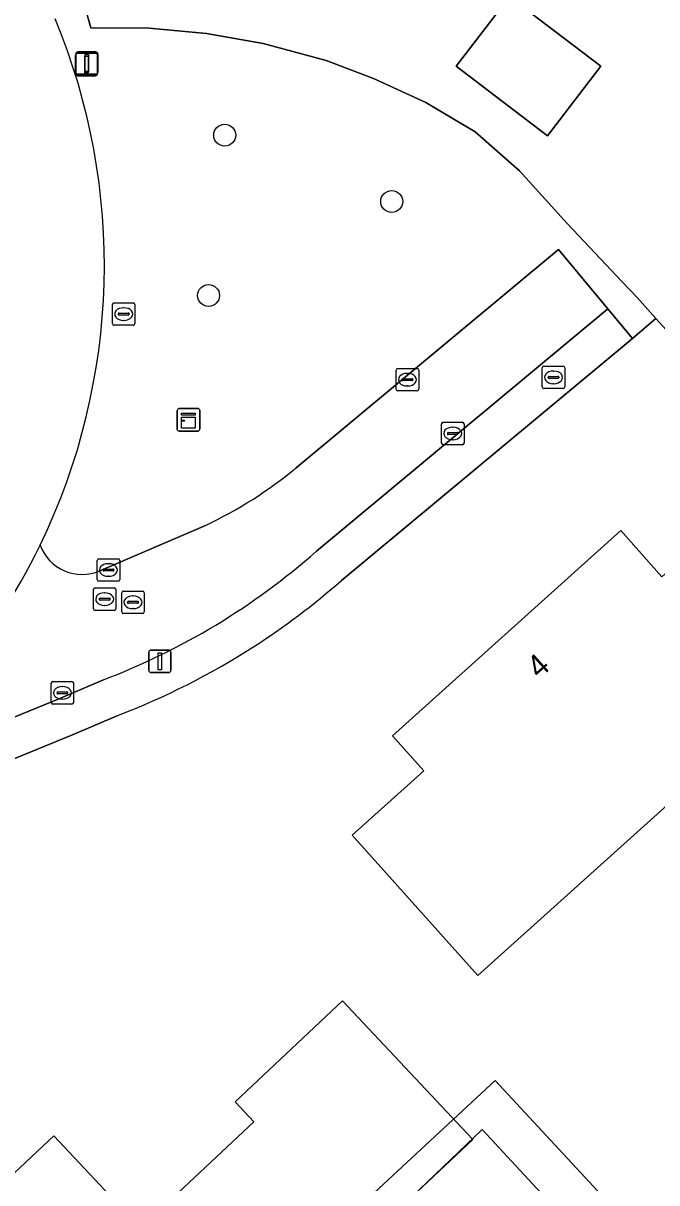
# Model space of a CAD drawing. Extents: x 163266 to 164362, y 381528 to 382286.
# Drawn here: x 163853.6 to 163881.8, y 381685.3 to 381736.9 of the extents above; entities that cross this region are included whole.
import ezdxf

# ---------------------------------------------------------------- set-up
doc = ezdxf.new("R2010")
doc.units = 0
for name, color, linetype in [('IMGEO_Boom', 7, 'Continuous'), ('IMGEO_Brandkraan', 7, 'Continuous'), ('IMGEO_Erf', 7, 'Continuous'), ('IMGEO_Groenvoorziening', 7, 'Continuous'), ('IMGEO_Hek', 7, 'Continuous'), ('IMGEO_Kast', 7, 'Continuous'), ('IMGEO_Kolk', 7, 'Continuous'), ('IMGEO_Lichtmast', 7, 'Continuous'), ('IMGEO_Pand', 7, 'Continuous'), ('IMGEO_Pand_nummerreeks', 7, 'Continuous'), ('IMGEO_Pand_vergunning_verleend', 7, 'Continuous'), ('IMGEO_Rijbaan_lokaal_gesloten', 7, 'Continuous'), ('IMGEO_Rijbaan_lokaal_open', 7, 'Continuous'), ('IMGEO_Rioolput', 7, 'Continuous'), ('IMGEO_Voetpad_open', 7, 'Continuous')]:
    doc.layers.add(name, color=color, linetype=linetype)

msp = doc.modelspace()

# ---------------------------------------------------------------- linework, layer by layer
at = {"layer": 'IMGEO_Boom'}
for centre in [(163862.574, 381731.873), (163870.006, 381728.922), (163861.854, 381724.742)]:
    msp.add_circle(centre, 0.489, dxfattribs=at)
at = {"layer": 'IMGEO_Brandkraan'}
for p, q in [((163857.578, 381723.488), (163857.578, 381724.34)), ((163857.653, 381724.414), (163858.505, 381724.414)), ((163858.066, 381724.194), (163858.091, 381724.194)), ((163858.579, 381724.34), (163858.579, 381723.488)), ((163857.837, 381723.908), (163857.837, 381723.92)), ((163858.275, 381723.871), (163857.877, 381723.871)), ((163857.88, 381723.957), (163858.278, 381723.957)), ((163858.321, 381723.92), (163858.321, 381723.908)), ((163858.505, 381723.414), (163857.653, 381723.414)), ((163858.089, 381723.634), (163858.064, 381723.634)), ((163876.705, 381720.671), (163876.705, 381721.523)), ((163876.78, 381721.597), (163877.632, 381721.597)), ((163876.964, 381721.091), (163876.964, 381721.103)), ((163877.007, 381721.14), (163877.405, 381721.14)), ((163877.193, 381721.377), (163877.218, 381721.377)), ((163877.448, 381721.103), (163877.448, 381721.091)), ((163877.706, 381721.523), (163877.706, 381720.671)), ((163877.632, 381720.597), (163876.78, 381720.597)), ((163877.402, 381721.054), (163877.004, 381721.054)), ((163877.216, 381720.817), (163877.191, 381720.817))]:
    msp.add_line(p, q, dxfattribs=at)
for points in [[(163857.578, 381723.488), (163857.578, 381724.34)], [(163857.653, 381724.414), (163858.505, 381724.414)], [(163858.579, 381724.34), (163858.579, 381723.488)], [(163858.505, 381723.414), (163857.653, 381723.414)], [(163876.705, 381720.671), (163876.705, 381721.523)], [(163876.78, 381721.597), (163877.632, 381721.597)], [(163877.706, 381721.523), (163877.706, 381720.671)], [(163877.632, 381720.597), (163876.78, 381720.597)]]:
    msp.add_lwpolyline(points, dxfattribs=at)
for centre, radius, start, end in [((163857.655, 381724.338), 0.0765, 91.552, 178.448), ((163857.655, 381724.338), 0.0765, 91.552, 178.448), ((163858.503, 381724.338), 0.0765, 1.552, 88.448), ((163858.503, 381724.338), 0.0765, 1.552, 88.448), ((163857.877, 381723.917), 0.0403, 85.8775, 175.7526), ((163857.874, 381723.907), 0.0366, 178.938, 274.7102), ((163858.278, 381723.914), 0.043, 264.8664, 352.4533), ((163858.282, 381723.919), 0.0386, 1.7309, 96.639), ((163857.655, 381723.49), 0.0765, 181.552, 268.448), ((163857.655, 381723.49), 0.0765, 181.552, 268.448), ((163858.503, 381723.49), 0.0765, 271.552, 358.448), ((163858.503, 381723.49), 0.0765, 271.552, 358.448), ((163876.782, 381721.521), 0.0765, 91.552, 178.448), ((163876.782, 381721.521), 0.0765, 91.552, 178.448), ((163877.004, 381721.1), 0.0403, 85.8775, 175.7526), ((163877.001, 381721.09), 0.0366, 178.938, 274.7102), ((163877.405, 381721.097), 0.043, 264.8664, 352.4533), ((163877.409, 381721.102), 0.0386, 1.7309, 96.639), ((163877.63, 381721.521), 0.0765, 1.552, 88.448), ((163877.63, 381721.521), 0.0765, 1.552, 88.448), ((163876.782, 381720.673), 0.0765, 181.552, 268.448), ((163876.782, 381720.673), 0.0765, 181.552, 268.448), ((163877.63, 381720.673), 0.0765, 271.552, 358.448), ((163877.63, 381720.673), 0.0765, 271.552, 358.448)]:
    msp.add_arc(centre, radius, start, end, dxfattribs=at)
for centre, major_axis, ratio, start_param, end_param in [((163858.065, 381723.914), (-0.387, 0.002), 0.722429, 4.712389, 7.853982), ((163858.09, 381723.914), (-0.39, 0.002), 0.717154, 1.570796, 4.712389), ((163877.192, 381721.097), (-0.387, 0.002), 0.722429, 4.712389, 7.853982), ((163877.217, 381721.097), (-0.39, 0.002), 0.717154, 1.570796, 4.712389)]:
    msp.add_ellipse(centre, major_axis=major_axis, ratio=ratio, start_param=start_param, end_param=end_param, dxfattribs=at)
at = {"layer": 'IMGEO_Erf'}
for points in [[(163850.883, 381757.141), (163856.616, 381736.644), (163859.21, 381736.627), (163861.761, 381736.402), (163864.289, 381735.951), (163867.084, 381735.196), (163869.192, 381734.396), (163871.524, 381733.322), (163873.711, 381732.021), (163875.685, 381730.29), (163877.82, 381727.931), (163880.26, 381725.345), (163880.92, 381724.646), (163881.763, 381723.722), (163902.744, 381700.712)], [(163813.536, 381684.558), (163844.648, 381661.7), (163845.156, 381661.33), (163866.027, 381679.982), (163874.024, 381687.636), (163880.414, 381680.758), (163881.837, 381682.029), (163902.744, 381700.712), (163881.763, 381723.722)], [(163881.763, 381723.722), (163880.716, 381722.833), (163867.763, 381712.065)], [(163857.819, 381706.063), (163855.804, 381705.198), (163814.888, 381688.458)], [(163880.414, 381680.758), (163874.024, 381687.636), (163866.027, 381679.982)]]:
    msp.add_lwpolyline(points, dxfattribs=at)
for points in [[(163876.932, 381731.837), (163872.867, 381734.948), (163875.238, 381738.047), (163879.303, 381734.936)], [(163880.198, 381714.282), (163882.017, 381712.229), (163886.456, 381716.202), (163895.326, 381706.295), (163894.818, 381705.864), (163894.515, 381706.203), (163894.839, 381706.494), (163892.959, 381708.595), (163890.6, 381706.433), (163890.157, 381706.93), (163888.281, 381705.256), (163888.721, 381704.764), (163888.381, 381704.461), (163886.839, 381706.189), (163873.843, 381694.498), (163868.244, 381700.731), (163871.439, 381703.601), (163870.041, 381705.157)]]:
    msp.add_lwpolyline(points, close=True, dxfattribs=at)
for centre, radius, start, end in [((163846.239, 381736.522), 32.58, 302.6721, 311.3512), ((163846.046, 381736.837), 32.949, 290.9359, 302.6588)]:
    msp.add_arc(centre, radius, start, end, dxfattribs=at)
at = {"layer": 'IMGEO_Groenvoorziening'}
for points in [[(163873.711, 381732.021), (163871.524, 381733.322), (163869.192, 381734.396), (163867.084, 381735.196), (163864.289, 381735.951), (163861.761, 381736.402), (163859.21, 381736.627), (163856.616, 381736.644), (163850.883, 381757.141), (163850.503, 381759.694), (163850.811, 381762.261), (163851.842, 381764.638), (163852.921, 381766.145), (163853.342, 381766.734), (163856.492, 381769.479), (163855.866, 381769.846), (163850.5, 381769.785), (163849.572, 381768.615)], [(163865.758, 381717.08), (163877.43, 381726.793), (163879.625, 381724.148), (163880.716, 381722.833), (163881.763, 381723.722), (163880.92, 381724.646), (163880.26, 381725.345), (163877.82, 381727.931), (163875.685, 381730.29), (163873.711, 381732.021)], [(163857.017, 381712.489), (163861.719, 381714.515)]]:
    msp.add_lwpolyline(points, dxfattribs=at)
for centre, radius, start, end in [((163828.687, 381726.081), 28.532, 334.1457, 22.6048), ((163853.499, 381731.921), 19.249, 295.2785, 309.5573), ((163856.234, 381714.319), 1.991, 199.9763, 293.1687)]:
    msp.add_arc(centre, radius, start, end, dxfattribs=at)
at = {"layer": 'IMGEO_Hek'}
for points in [[(163856.616, 381736.644), (163850.883, 381757.141), (163850.503, 381759.694), (163850.811, 381762.261), (163851.842, 381764.638), (163852.921, 381766.145)], [(163856.616, 381736.644), (163859.21, 381736.627), (163861.761, 381736.402), (163864.289, 381735.951), (163867.084, 381735.196), (163869.192, 381734.396), (163871.524, 381733.322), (163873.711, 381732.021), (163875.685, 381730.29), (163877.82, 381727.931)], [(163877.82, 381727.931), (163880.26, 381725.345), (163880.92, 381724.646), (163881.763, 381723.722), (163902.744, 381700.712)], [(163881.837, 381682.029), (163874.606, 381689.824), (163846.633, 381663.876), (163845.156, 381661.33)]]:
    msp.add_lwpolyline(points, dxfattribs=at)
at = {"layer": 'IMGEO_Kast'}
for p, q in [((163860.461, 381718.786), (163860.461, 381719.627)), ((163860.461, 381719.627), (163860.461, 381718.786)), ((163860.536, 381719.711), (163861.377, 381719.711)), ((163861.377, 381719.711), (163860.536, 381719.711)), ((163861.461, 381719.636), (163861.461, 381718.795)), ((163861.461, 381718.795), (163861.461, 381719.636)), ((163861.386, 381718.711), (163860.545, 381718.711)), ((163860.545, 381718.711), (163861.386, 381718.711))]:
    msp.add_line(p, q, dxfattribs=at)
for points in [[(163860.656, 381719.501), (163861.256, 381719.501), (163861.256, 381719.416), (163860.656, 381719.416), (163860.656, 381719.501)], [(163860.656, 381719.326), (163861.256, 381719.326), (163861.256, 381718.837), (163860.656, 381718.837), (163860.656, 381719.326)]]:
    msp.add_lwpolyline(points, dxfattribs=at)
msp.add_circle((163860.74, 381719.175), 0.0377, dxfattribs=at)
for centre, start, end in [((163860.539, 381719.633), 92.4484, 184.2845), ((163860.539, 381719.633), 92.4484, 184.2845), ((163861.383, 381719.633), 2.4484, 94.2845), ((163861.383, 381719.633), 2.4484, 94.2845), ((163860.539, 381718.789), 182.4484, 274.2845), ((163860.539, 381718.789), 182.4484, 274.2845), ((163861.383, 381718.789), 272.4484, 4.2845), ((163861.383, 381718.789), 272.4484, 4.2845)]:
    msp.add_arc(centre, 0.0779, start, end, dxfattribs=at)
at = {"layer": 'IMGEO_Kolk'}
for p, q in [((163870.203, 381720.571), (163870.203, 381721.423)), ((163870.278, 381721.497), (163871.13, 381721.497)), ((163870.691, 381721.277), (163870.716, 381721.277)), ((163871.204, 381721.423), (163871.204, 381720.571)), ((163870.462, 381720.991), (163870.462, 381721.003)), ((163870.9, 381720.954), (163870.502, 381720.954)), ((163870.505, 381721.04), (163870.903, 381721.04)), ((163870.714, 381720.717), (163870.689, 381720.717)), ((163870.946, 381721.003), (163870.946, 381720.991)), ((163871.13, 381720.497), (163870.278, 381720.497)), ((163872.221, 381718.177), (163872.221, 381719.029)), ((163872.296, 381719.103), (163873.148, 381719.103)), ((163873.222, 381719.029), (163873.222, 381718.177)), ((163872.48, 381718.597), (163872.48, 381718.609)), ((163872.918, 381718.56), (163872.52, 381718.56)), ((163872.523, 381718.646), (163872.921, 381718.646)), ((163872.709, 381718.883), (163872.734, 381718.883)), ((163872.964, 381718.609), (163872.964, 381718.597)), ((163873.148, 381718.103), (163872.296, 381718.103)), ((163872.732, 381718.323), (163872.707, 381718.323)), ((163856.899, 381712.104), (163856.899, 381712.956)), ((163856.974, 381713.03), (163857.826, 381713.03)), ((163857.9, 381712.956), (163857.9, 381712.104)), ((163857.158, 381712.524), (163857.158, 381712.536)), ((163857.596, 381712.487), (163857.198, 381712.487)), ((163857.201, 381712.573), (163857.599, 381712.573)), ((163857.387, 381712.81), (163857.412, 381712.81)), ((163857.642, 381712.536), (163857.642, 381712.524)), ((163857.826, 381712.03), (163856.974, 381712.03)), ((163857.41, 381712.25), (163857.385, 381712.25)), ((163854.851, 381706.639), (163854.851, 381707.491)), ((163854.926, 381707.565), (163855.778, 381707.565)), ((163855.339, 381707.345), (163855.364, 381707.345)), ((163855.852, 381707.491), (163855.852, 381706.639)), ((163855.11, 381707.059), (163855.11, 381707.071)), ((163855.548, 381707.022), (163855.15, 381707.022)), ((163855.153, 381707.108), (163855.551, 381707.108)), ((163855.362, 381706.785), (163855.337, 381706.785)), ((163855.594, 381707.071), (163855.594, 381707.059)), ((163855.778, 381706.565), (163854.926, 381706.565))]:
    msp.add_line(p, q, dxfattribs=at)
for points in [[(163870.203, 381720.571), (163870.203, 381721.423)], [(163870.278, 381721.497), (163871.13, 381721.497)], [(163871.204, 381721.423), (163871.204, 381720.571)], [(163871.13, 381720.497), (163870.278, 381720.497)], [(163872.221, 381718.177), (163872.221, 381719.029)], [(163872.296, 381719.103), (163873.148, 381719.103)], [(163873.222, 381719.029), (163873.222, 381718.177)], [(163873.148, 381718.103), (163872.296, 381718.103)], [(163856.899, 381712.104), (163856.899, 381712.956)], [(163856.974, 381713.03), (163857.826, 381713.03)], [(163857.9, 381712.956), (163857.9, 381712.104)], [(163857.826, 381712.03), (163856.974, 381712.03)], [(163854.851, 381706.639), (163854.851, 381707.491)], [(163854.926, 381707.565), (163855.778, 381707.565)], [(163855.852, 381707.491), (163855.852, 381706.639)], [(163855.778, 381706.565), (163854.926, 381706.565)]]:
    msp.add_lwpolyline(points, dxfattribs=at)
for centre, radius, start, end in [((163870.28, 381721.421), 0.0765, 91.552, 178.448), ((163870.28, 381721.421), 0.0765, 91.552, 178.448), ((163871.128, 381721.421), 0.0765, 1.552, 88.448), ((163871.128, 381721.421), 0.0765, 1.552, 88.448), ((163870.28, 381720.573), 0.0765, 181.552, 268.448), ((163870.28, 381720.573), 0.0765, 181.552, 268.448), ((163870.502, 381721), 0.0403, 85.8775, 175.7526), ((163870.499, 381720.99), 0.0366, 178.938, 274.7102), ((163870.903, 381720.997), 0.043, 264.8664, 352.4533), ((163870.907, 381721.002), 0.0386, 1.7309, 96.639), ((163871.128, 381720.573), 0.0765, 271.552, 358.448), ((163871.128, 381720.573), 0.0765, 271.552, 358.448), ((163872.298, 381719.027), 0.0765, 91.552, 178.448), ((163872.298, 381719.027), 0.0765, 91.552, 178.448), ((163873.146, 381719.027), 0.0765, 1.552, 88.448), ((163873.146, 381719.027), 0.0765, 1.552, 88.448), ((163872.52, 381718.606), 0.0403, 85.8775, 175.7526), ((163872.517, 381718.596), 0.0366, 178.938, 274.7102), ((163872.921, 381718.603), 0.043, 264.8664, 352.4533), ((163872.925, 381718.608), 0.0386, 1.7309, 96.639), ((163872.298, 381718.179), 0.0765, 181.552, 268.448), ((163872.298, 381718.179), 0.0765, 181.552, 268.448), ((163873.146, 381718.179), 0.0765, 271.552, 358.448), ((163873.146, 381718.179), 0.0765, 271.552, 358.448), ((163856.976, 381712.954), 0.0765, 91.552, 178.448), ((163856.976, 381712.954), 0.0765, 91.552, 178.448), ((163857.824, 381712.954), 0.0765, 1.552, 88.448), ((163857.824, 381712.954), 0.0765, 1.552, 88.448), ((163857.198, 381712.533), 0.0403, 85.8775, 175.7526), ((163857.195, 381712.523), 0.0366, 178.938, 274.7102), ((163857.599, 381712.53), 0.043, 264.8664, 352.4533), ((163857.603, 381712.535), 0.0386, 1.7309, 96.639), ((163856.976, 381712.106), 0.0765, 181.552, 268.448), ((163856.976, 381712.106), 0.0765, 181.552, 268.448), ((163857.824, 381712.106), 0.0765, 271.552, 358.448), ((163857.824, 381712.106), 0.0765, 271.552, 358.448), ((163854.928, 381707.489), 0.0765, 91.552, 178.448), ((163854.928, 381707.489), 0.0765, 91.552, 178.448), ((163855.776, 381707.489), 0.0765, 1.552, 88.448), ((163855.776, 381707.489), 0.0765, 1.552, 88.448), ((163855.15, 381707.068), 0.0403, 85.8775, 175.7526), ((163855.147, 381707.058), 0.0366, 178.938, 274.7102), ((163855.551, 381707.065), 0.043, 264.8664, 352.4533), ((163855.555, 381707.07), 0.0386, 1.7309, 96.639), ((163854.928, 381706.641), 0.0765, 181.552, 268.448), ((163854.928, 381706.641), 0.0765, 181.552, 268.448), ((163855.776, 381706.641), 0.0765, 271.552, 358.448), ((163855.776, 381706.641), 0.0765, 271.552, 358.448)]:
    msp.add_arc(centre, radius, start, end, dxfattribs=at)
for centre, major_axis, ratio, start_param, end_param in [((163870.69, 381720.997), (-0.387, 0.002), 0.722429, 4.712389, 7.853982), ((163870.715, 381720.997), (-0.39, 0.002), 0.717154, 1.570796, 4.712389), ((163872.708, 381718.603), (-0.387, 0.002), 0.722429, 4.712389, 7.853982), ((163872.733, 381718.603), (-0.39, 0.002), 0.717154, 1.570796, 4.712389), ((163857.386, 381712.53), (-0.387, 0.002), 0.722429, 4.712389, 7.853982), ((163857.411, 381712.53), (-0.39, 0.002), 0.717154, 1.570796, 4.712389), ((163855.338, 381707.065), (-0.387, 0.002), 0.722429, 4.712389, 7.853982), ((163855.363, 381707.065), (-0.39, 0.002), 0.717154, 1.570796, 4.712389)]:
    msp.add_ellipse(centre, major_axis=major_axis, ratio=ratio, start_param=start_param, end_param=end_param, dxfattribs=at)
at = {"layer": 'IMGEO_Lichtmast'}
for p, q in [((163856.044, 381735.58), (163856.834, 381735.58)), ((163856.834, 381735.58), (163856.044, 381735.58)), ((163855.927, 381734.618), (163855.927, 381735.418)), ((163855.927, 381735.418), (163855.927, 381734.618)), ((163855.944, 381734.68), (163855.944, 381735.48)), ((163855.944, 381735.48), (163855.944, 381734.68)), ((163856.027, 381735.518), (163856.817, 381735.518)), ((163856.817, 381735.518), (163856.027, 381735.518)), ((163856.917, 381735.418), (163856.917, 381734.618)), ((163856.917, 381734.618), (163856.917, 381735.418)), ((163856.934, 381735.48), (163856.934, 381734.68)), ((163856.934, 381734.68), (163856.934, 381735.48)), ((163856.817, 381734.518), (163856.027, 381734.518)), ((163856.027, 381734.518), (163856.817, 381734.518)), ((163856.834, 381734.58), (163856.044, 381734.58)), ((163856.044, 381734.58), (163856.834, 381734.58)), ((163859.19, 381708.067), (163859.19, 381708.867)), ((163859.19, 381708.867), (163859.19, 381708.067)), ((163859.29, 381708.967), (163860.08, 381708.967)), ((163860.08, 381708.967), (163859.29, 381708.967)), ((163860.18, 381708.867), (163860.18, 381708.067)), ((163860.18, 381708.067), (163860.18, 381708.867)), ((163860.08, 381707.967), (163859.29, 381707.967)), ((163859.29, 381707.967), (163860.08, 381707.967))]:
    msp.add_line(p, q, dxfattribs=at)
for points in [[(163856.347, 381735.393), (163856.497, 381735.393), (163856.497, 381734.643), (163856.347, 381734.643), (163856.347, 381735.393)], [(163856.364, 381735.455), (163856.514, 381735.455), (163856.514, 381734.705), (163856.364, 381734.705), (163856.364, 381735.455)], [(163859.61, 381708.842), (163859.76, 381708.842), (163859.76, 381708.092), (163859.61, 381708.092), (163859.61, 381708.842)]]:
    msp.add_lwpolyline(points, dxfattribs=at)
for centre, start, end in [((163856.044, 381735.48), 90, 180), ((163856.044, 381735.48), 90, 180), ((163856.834, 381735.48), 0, 90), ((163856.834, 381735.48), 360, 90), ((163856.027, 381735.418), 90, 180), ((163856.027, 381735.418), 90, 180), ((163856.817, 381735.418), 0, 90), ((163856.817, 381735.418), 360, 90), ((163856.027, 381734.618), 180, 270), ((163856.027, 381734.618), 180, 270), ((163856.044, 381734.68), 180, 270), ((163856.044, 381734.68), 180, 270), ((163856.817, 381734.618), 270, 0), ((163856.817, 381734.618), 270, 0), ((163856.834, 381734.68), 270, 0), ((163856.834, 381734.68), 270, 0), ((163859.29, 381708.867), 90, 180), ((163859.29, 381708.867), 90, 180), ((163860.08, 381708.867), 0, 90), ((163860.08, 381708.867), 360, 90), ((163859.29, 381708.067), 180, 270), ((163859.29, 381708.067), 180, 270), ((163860.08, 381708.067), 270, 0), ((163860.08, 381708.067), 270, 0)]:
    msp.add_arc(centre, 0.1, start, end, dxfattribs=at)
at = {"layer": 'IMGEO_Pand'}
for points in [[(163876.932, 381731.837), (163879.303, 381734.936), (163875.238, 381738.047), (163872.867, 381734.948)], [(163890.6, 381706.433), (163892.959, 381708.595), (163894.839, 381706.494), (163894.515, 381706.203), (163894.818, 381705.864), (163895.326, 381706.295), (163886.456, 381716.202), (163882.017, 381712.229), (163880.198, 381714.282), (163870.041, 381705.157), (163871.439, 381703.601), (163868.244, 381700.731), (163873.843, 381694.498), (163886.839, 381706.189), (163888.381, 381704.461), (163888.721, 381704.764), (163888.281, 381705.256), (163890.157, 381706.93)]]:
    msp.add_lwpolyline(points, close=True, dxfattribs=at)
at = {"layer": 'IMGEO_Pand_vergunning_verleend'}
msp.add_lwpolyline([(163833.26, 381683.642), (163839.611, 381689.603), (163847.921, 381680.749), (163854.966, 381687.362), (163858.823, 381683.254), (163863.864, 381687.986), (163863.032, 381688.872), (163867.819, 381693.365), (163873.615, 381687.19), (163863.409, 381677.61), (163861.905, 381679.366), (163852.886, 381671.64), (163848.73, 381676.491), (163842.79, 381671.403), (163835.711, 381678.946), (163836.751, 381679.922)], close=True, dxfattribs=at)
at = {"layer": 'IMGEO_Rijbaan_lokaal_gesloten'}
for centre, radius, start, end in [((163828.687, 381726.081), 28.532, 334.1457, 22.6048), ((163828.698, 381726.072), 28.517, 304.515, 334.1529)]:
    msp.add_arc(centre, radius, start, end, dxfattribs=at)
at = {"layer": 'IMGEO_Rijbaan_lokaal_open'}
for points in [[(163879.625, 381724.148), (163877.43, 381726.793), (163865.758, 381717.08)], [(163866.653, 381713.363), (163879.625, 381724.148)], [(163861.719, 381714.515), (163857.017, 381712.489)], [(163844.857, 381702.574), (163855.164, 381706.782), (163857.177, 381707.647)]]:
    msp.add_lwpolyline(points, dxfattribs=at)
for centre, radius, start, end in [((163853.499, 381731.921), 19.249, 295.2785, 309.5573), ((163828.698, 381726.072), 28.517, 304.515, 334.1529), ((163856.234, 381714.319), 1.991, 199.9763, 293.1687), ((163846.12, 381736.69), 31.077, 290.8424, 311.3551)]:
    msp.add_arc(centre, radius, start, end, dxfattribs=at)
at = {"layer": 'IMGEO_Rioolput'}
for p, q in [((163856.733, 381710.809), (163856.733, 381711.661)), ((163856.808, 381711.735), (163857.66, 381711.735)), ((163857.221, 381711.515), (163857.246, 381711.515)), ((163857.734, 381711.661), (163857.734, 381710.809)), ((163857.991, 381710.668), (163857.991, 381711.52)), ((163858.066, 381711.594), (163858.918, 381711.594)), ((163858.479, 381711.374), (163858.504, 381711.374)), ((163858.992, 381711.52), (163858.992, 381710.668)), ((163856.992, 381711.229), (163856.992, 381711.241)), ((163857.43, 381711.192), (163857.032, 381711.192)), ((163857.035, 381711.278), (163857.433, 381711.278)), ((163857.244, 381710.955), (163857.219, 381710.955)), ((163857.476, 381711.241), (163857.476, 381711.229)), ((163858.25, 381711.088), (163858.25, 381711.1)), ((163858.688, 381711.051), (163858.29, 381711.051)), ((163858.293, 381711.137), (163858.691, 381711.137)), ((163858.502, 381710.814), (163858.477, 381710.814)), ((163858.734, 381711.1), (163858.734, 381711.088)), ((163857.66, 381710.735), (163856.808, 381710.735)), ((163858.918, 381710.594), (163858.066, 381710.594))]:
    msp.add_line(p, q, dxfattribs=at)
for points in [[(163856.733, 381710.809), (163856.733, 381711.661)], [(163856.808, 381711.735), (163857.66, 381711.735)], [(163857.734, 381711.661), (163857.734, 381710.809)], [(163857.991, 381710.668), (163857.991, 381711.52)], [(163858.066, 381711.594), (163858.918, 381711.594)], [(163858.992, 381711.52), (163858.992, 381710.668)], [(163857.66, 381710.735), (163856.808, 381710.735)], [(163858.918, 381710.594), (163858.066, 381710.594)]]:
    msp.add_lwpolyline(points, dxfattribs=at)
for centre, radius, start, end in [((163856.81, 381711.659), 0.0765, 91.552, 178.448), ((163856.81, 381711.659), 0.0765, 91.552, 178.448), ((163857.658, 381711.659), 0.0765, 1.552, 88.448), ((163857.658, 381711.659), 0.0765, 1.552, 88.448), ((163858.068, 381711.518), 0.0765, 91.552, 178.448), ((163858.068, 381711.518), 0.0765, 91.552, 178.448), ((163858.916, 381711.518), 0.0765, 1.552, 88.448), ((163858.916, 381711.518), 0.0765, 1.552, 88.448), ((163856.81, 381710.811), 0.0765, 181.552, 268.448), ((163856.81, 381710.811), 0.0765, 181.552, 268.448), ((163857.032, 381711.238), 0.0403, 85.8775, 175.7526), ((163857.029, 381711.228), 0.0366, 178.938, 274.7102), ((163857.433, 381711.235), 0.043, 264.8664, 352.4533), ((163857.437, 381711.24), 0.0386, 1.7309, 96.639), ((163857.658, 381710.811), 0.0765, 271.552, 358.448), ((163857.658, 381710.811), 0.0765, 271.552, 358.448), ((163858.29, 381711.097), 0.0403, 85.8775, 175.7526), ((163858.287, 381711.087), 0.0366, 178.938, 274.7102), ((163858.691, 381711.094), 0.043, 264.8664, 352.4533), ((163858.695, 381711.099), 0.0386, 1.7309, 96.639), ((163858.068, 381710.67), 0.0765, 181.552, 268.448), ((163858.068, 381710.67), 0.0765, 181.552, 268.448), ((163858.916, 381710.67), 0.0765, 271.552, 358.448), ((163858.916, 381710.67), 0.0765, 271.552, 358.448)]:
    msp.add_arc(centre, radius, start, end, dxfattribs=at)
for centre, major_axis, ratio, start_param, end_param in [((163857.22, 381711.235), (-0.387, 0.002), 0.722429, 4.712389, 7.853982), ((163857.245, 381711.235), (-0.39, 0.002), 0.717154, 1.570796, 4.712389), ((163858.478, 381711.094), (-0.387, 0.002), 0.722429, 4.712389, 7.853982), ((163858.503, 381711.094), (-0.39, 0.002), 0.717154, 1.570796, 4.712389)]:
    msp.add_ellipse(centre, major_axis=major_axis, ratio=ratio, start_param=start_param, end_param=end_param, dxfattribs=at)
at = {"layer": 'IMGEO_Voetpad_open'}
for points in [[(163867.763, 381712.065), (163880.716, 381722.833), (163879.625, 381724.148), (163866.653, 381713.363)], [(163857.177, 381707.647), (163855.164, 381706.782), (163844.857, 381702.574), (163840.235, 381700.687), (163815.256, 381690.453), (163813.682, 381689.801)], [(163855.804, 381705.198), (163857.819, 381706.063)], [(163814.888, 381688.458), (163855.804, 381705.198)]]:
    msp.add_lwpolyline(points, dxfattribs=at)
for centre, radius, start, end in [((163846.12, 381736.69), 31.077, 290.8424, 311.3551), ((163846.239, 381736.522), 32.58, 302.6721, 311.3512), ((163846.046, 381736.837), 32.949, 290.9359, 302.6588)]:
    msp.add_arc(centre, radius, start, end, dxfattribs=at)

# ---------------------------------------------------------------- texts
at = {"layer": 'IMGEO_Pand_nummerreeks'}
msp.add_text('4', height=1, rotation=41.9348, dxfattribs=at).set_placement((163876.566, 381707.658))

doc.saveas('drawing.dxf')
